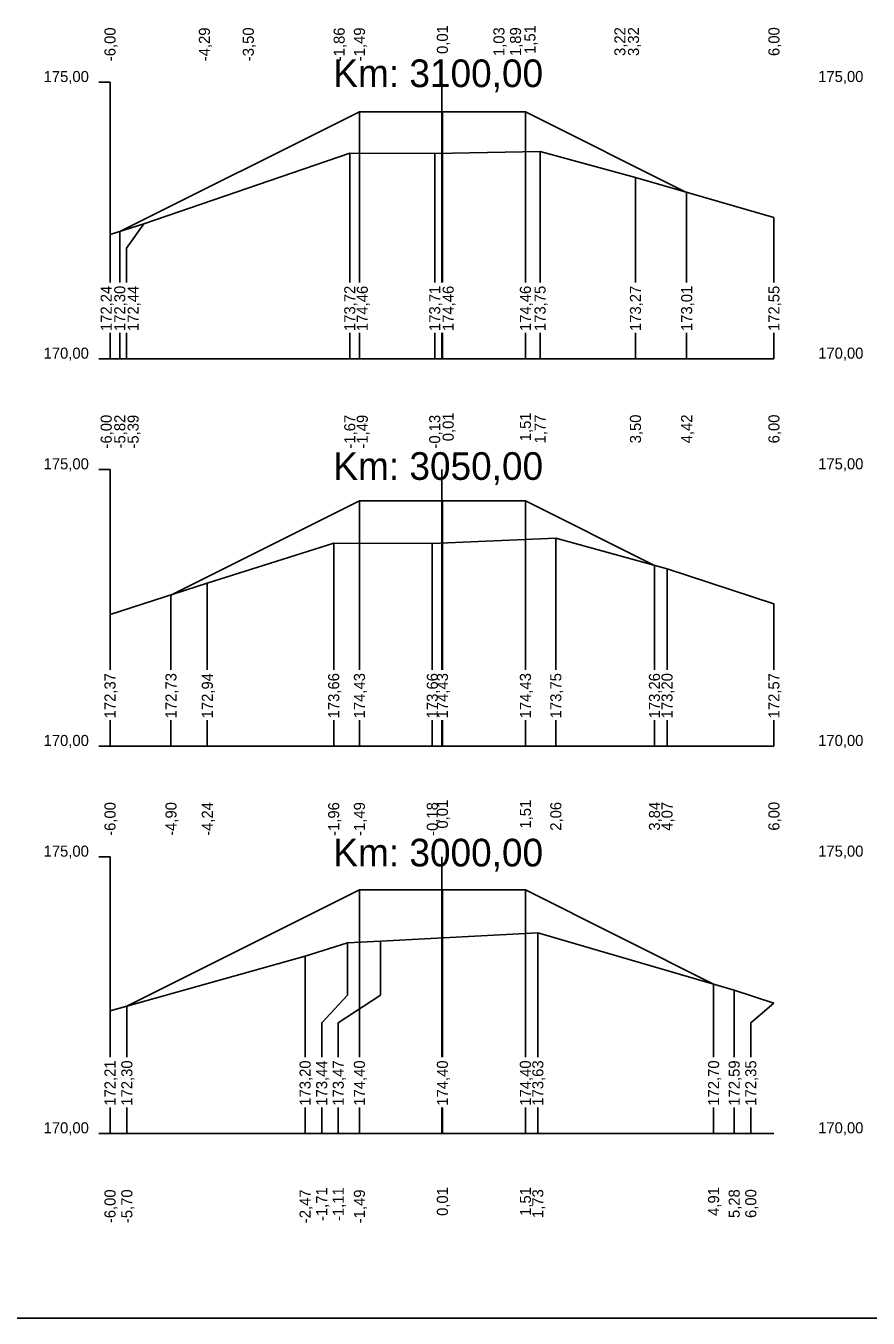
# Model space of a CAD drawing. Extents: x -614174 to -599765, y -1185887 to -1181080.
# Drawn here: x -601047.91 to -601032.69, y -1184533.61 to -1184510.25 of the extents above; entities that cross this region are included whole.
import ezdxf

# ---------------------------------------------------------------- set-up
doc = ezdxf.new("R2010")
doc.units = 0
for name, color, linetype in [('11', 7, 'Continuous'), ('16', 7, 'Continuous'), ('21', 7, 'Continuous'), ('28', 7, 'Continuous'), ('59', 7, 'Continuous'), ('8', 7, 'Continuous'), ('návrh', 7, 'Continuous')]:
    doc.layers.add(name, color=color, linetype=linetype)

msp = doc.modelspace()

# ---------------------------------------------------------------- linework, layer by layer
for points in [[(-601046.212, -1184513.972), (-601041.881, -1184511.806), (-601040.381, -1184511.806), (-601038.881, -1184511.806), (-601035.966, -1184513.264)], [(-601041.881, -1184511.806), (-601041.881, -1184511.806), (-601041.881, -1184511.806)], [(-601040.381, -1184511.806), (-601040.381, -1184511.806), (-601040.381, -1184511.806)], [(-601038.881, -1184511.806), (-601038.881, -1184511.806), (-601038.881, -1184511.806)], [(-601046.389, -1184514.028), (-601045.775, -1184513.834), (-601042.055, -1184512.555), (-601040.52, -1184512.559), (-601038.616, -1184512.523), (-601036.891, -1184512.998), (-601034.389, -1184513.717)], [(-601046.212, -1184513.972), (-601046.212, -1184513.972), (-601046.212, -1184513.972)], [(-601045.287, -1184520.541), (-601041.881, -1184518.838), (-601040.381, -1184518.838), (-601038.881, -1184518.838), (-601036.548, -1184520.005)], [(-601041.881, -1184518.838), (-601041.881, -1184518.838), (-601041.881, -1184518.838)], [(-601040.381, -1184518.838), (-601040.381, -1184518.838), (-601040.381, -1184518.838)], [(-601038.881, -1184518.838), (-601038.881, -1184518.838), (-601038.881, -1184518.838)], [(-601046.389, -1184520.896), (-601044.63, -1184520.329), (-601042.346, -1184519.605), (-601040.564, -1184519.611), (-601038.331, -1184519.515), (-601036.321, -1184520.067), (-601034.389, -1184520.702)], [(-601045.286, -1184520.541), (-601045.287, -1184520.541), (-601045.287, -1184520.541)], [(-601046.085, -1184527.972), (-601041.881, -1184525.87), (-601040.381, -1184525.87), (-601038.881, -1184525.87), (-601035.479, -1184527.571)], [(-601041.881, -1184525.87), (-601041.881, -1184525.87), (-601041.881, -1184525.87)], [(-601040.381, -1184525.87), (-601040.381, -1184525.87), (-601040.381, -1184525.87)], [(-601038.881, -1184525.87), (-601038.881, -1184525.87), (-601038.881, -1184525.87)], [(-601046.389, -1184528.057), (-601042.863, -1184527.069), (-601042.099, -1184526.825), (-601041.501, -1184526.799), (-601038.656, -1184526.644), (-601035.107, -1184527.68), (-601034.389, -1184527.916)], [(-601046.086, -1184527.972), (-601046.085, -1184527.972), (-601046.085, -1184527.972)]]:
    msp.add_lwpolyline(points)
at = {"layer": '11'}
for points in [[(-601041.881, -1184511.806), (-601041.881, -1184513.77), (-601041.881, -1184514.27), (-601041.881, -1184514.892)], [(-601040.381, -1184511.806), (-601040.381, -1184513.77), (-601040.381, -1184514.27), (-601040.381, -1184514.892)], [(-601038.881, -1184511.806), (-601038.881, -1184513.77), (-601038.881, -1184514.27), (-601038.881, -1184514.892)], [(-601038.616, -1184512.523), (-601038.616, -1184513.77), (-601038.616, -1184514.27), (-601038.616, -1184514.892)], [(-601042.055, -1184512.555), (-601042.055, -1184513.77), (-601042.055, -1184514.27), (-601042.055, -1184514.892)], [(-601040.52, -1184512.559), (-601040.52, -1184513.77), (-601040.52, -1184514.27), (-601040.52, -1184514.892)], [(-601036.891, -1184512.998), (-601036.891, -1184513.77), (-601036.891, -1184514.27), (-601036.891, -1184514.892)], [(-601035.966, -1184513.264), (-601035.966, -1184513.77), (-601035.966, -1184514.27), (-601035.966, -1184514.892)], [(-601046.389, -1184514.028), (-601046.389, -1184513.77), (-601046.389, -1184514.27), (-601046.389, -1184514.892)], [(-601045.775, -1184513.834), (-601045.775, -1184513.834), (-601046.089, -1184514.27), (-601046.089, -1184514.892)], [(-601034.389, -1184513.717), (-601034.389, -1184513.77), (-601034.389, -1184514.27), (-601034.389, -1184514.892)], [(-601046.212, -1184513.984), (-601046.212, -1184514.27), (-601046.212, -1184514.892)], [(-601046.389, -1184515.8), (-601046.389, -1184516.27)], [(-601046.212, -1184515.8), (-601046.212, -1184516.27)], [(-601046.089, -1184515.8), (-601046.089, -1184516.27)], [(-601042.055, -1184515.8), (-601042.055, -1184516.27)], [(-601041.881, -1184515.8), (-601041.881, -1184516.27)], [(-601040.52, -1184515.8), (-601040.52, -1184516.27)], [(-601040.381, -1184515.8), (-601040.381, -1184516.27)], [(-601038.881, -1184515.8), (-601038.881, -1184516.27)], [(-601038.616, -1184515.8), (-601038.616, -1184516.27)], [(-601036.891, -1184515.8), (-601036.891, -1184516.27)], [(-601035.966, -1184515.8), (-601035.966, -1184516.27)], [(-601034.389, -1184515.8), (-601034.389, -1184516.27)], [(-601041.881, -1184518.838), (-601041.881, -1184520.77), (-601041.881, -1184521.27), (-601041.881, -1184521.892)], [(-601040.381, -1184518.838), (-601040.381, -1184520.77), (-601040.381, -1184521.27), (-601040.381, -1184521.892)], [(-601038.881, -1184518.838), (-601038.881, -1184520.77), (-601038.881, -1184521.27), (-601038.881, -1184521.892)], [(-601038.331, -1184519.515), (-601038.331, -1184520.77), (-601038.331, -1184521.27), (-601038.331, -1184521.892)], [(-601042.346, -1184519.605), (-601042.346, -1184520.77), (-601042.346, -1184521.27), (-601042.346, -1184521.892)], [(-601040.564, -1184519.611), (-601040.564, -1184520.77), (-601040.564, -1184521.27), (-601040.564, -1184521.892)], [(-601036.548, -1184520.005), (-601036.548, -1184520.77), (-601036.548, -1184521.27), (-601036.548, -1184521.892)], [(-601036.321, -1184520.067), (-601036.321, -1184520.77), (-601036.321, -1184521.27), (-601036.321, -1184521.892)], [(-601044.63, -1184520.329), (-601044.63, -1184520.77), (-601044.63, -1184521.27), (-601044.63, -1184521.892)], [(-601045.287, -1184520.541), (-601045.287, -1184520.77), (-601045.287, -1184521.27), (-601045.287, -1184521.892)], [(-601034.389, -1184520.702), (-601034.389, -1184520.77), (-601034.389, -1184521.27), (-601034.389, -1184521.892)], [(-601046.389, -1184520.896), (-601046.389, -1184520.77), (-601046.389, -1184521.27), (-601046.389, -1184521.892)], [(-601046.389, -1184522.8), (-601046.389, -1184523.27)], [(-601045.287, -1184522.8), (-601045.287, -1184523.27)], [(-601044.63, -1184522.8), (-601044.63, -1184523.27)], [(-601042.346, -1184522.8), (-601042.346, -1184523.27)], [(-601041.881, -1184522.8), (-601041.881, -1184523.27)], [(-601040.564, -1184522.8), (-601040.564, -1184523.27)], [(-601040.381, -1184522.8), (-601040.381, -1184523.27)], [(-601038.881, -1184522.8), (-601038.881, -1184523.27)], [(-601038.331, -1184522.8), (-601038.331, -1184523.27)], [(-601036.548, -1184522.8), (-601036.548, -1184523.27)], [(-601036.321, -1184522.8), (-601036.321, -1184523.27)], [(-601034.389, -1184522.8), (-601034.389, -1184523.27)], [(-601041.881, -1184525.87), (-601041.881, -1184527.77), (-601041.881, -1184528.27), (-601041.881, -1184528.892)], [(-601040.381, -1184525.87), (-601040.381, -1184527.77), (-601040.381, -1184528.27), (-601040.381, -1184528.892)], [(-601038.881, -1184525.87), (-601038.881, -1184527.77), (-601038.881, -1184528.27), (-601038.881, -1184528.892)], [(-601038.656, -1184526.644), (-601038.656, -1184527.77), (-601038.656, -1184528.27), (-601038.656, -1184528.892)], [(-601042.099, -1184526.825), (-601042.099, -1184527.77), (-601042.563, -1184528.27), (-601042.563, -1184528.892)], [(-601041.501, -1184526.799), (-601041.501, -1184527.77), (-601042.263, -1184528.27), (-601042.263, -1184528.892)], [(-601042.863, -1184527.069), (-601042.863, -1184527.77), (-601042.863, -1184528.27), (-601042.863, -1184528.892)], [(-601035.479, -1184527.571), (-601035.479, -1184527.77), (-601035.479, -1184528.27), (-601035.479, -1184528.892)], [(-601035.107, -1184527.68), (-601035.107, -1184527.77), (-601035.107, -1184528.27), (-601035.107, -1184528.892)], [(-601046.389, -1184528.057), (-601046.389, -1184527.77), (-601046.389, -1184528.27), (-601046.389, -1184528.892)], [(-601034.389, -1184527.916), (-601034.807, -1184528.27), (-601034.807, -1184528.892)], [(-601046.085, -1184527.972), (-601046.085, -1184528.892)], [(-601046.389, -1184529.8), (-601046.389, -1184530.27)], [(-601046.085, -1184529.8), (-601046.085, -1184530.27)], [(-601042.863, -1184529.8), (-601042.863, -1184530.27)], [(-601042.563, -1184529.8), (-601042.563, -1184530.27)], [(-601042.263, -1184529.8), (-601042.263, -1184530.27)], [(-601041.881, -1184529.8), (-601041.881, -1184530.27)], [(-601040.381, -1184529.8), (-601040.381, -1184530.27)], [(-601038.881, -1184529.8), (-601038.881, -1184530.27)], [(-601038.656, -1184529.8), (-601038.656, -1184530.27)], [(-601035.479, -1184529.8), (-601035.479, -1184530.27)], [(-601035.107, -1184529.8), (-601035.107, -1184530.27)], [(-601034.807, -1184529.8), (-601034.807, -1184530.27)]]:
    msp.add_lwpolyline(points, dxfattribs=at)
at = {"layer": '16'}
for p, q in [((-601046.389, -1184516.27), (-601034.389, -1184516.27)), ((-601046.389, -1184523.27), (-601034.389, -1184523.27)), ((-601046.389, -1184530.27), (-601034.389, -1184530.27))]:
    msp.add_line(p, q, dxfattribs=at)
for points in [[(-601035.966, -1184513.264), (-601035.966, -1184513.264), (-601035.967, -1184513.264)], [(-601036.549, -1184520.005), (-601036.548, -1184520.005), (-601036.548, -1184520.005)], [(-601035.478, -1184527.572), (-601035.479, -1184527.571), (-601035.479, -1184527.571)]]:
    msp.add_lwpolyline(points, dxfattribs=at)
at = {"layer": '21'}
for p, q in [((-601046.589, -1184511.27), (-601046.389, -1184511.27)), ((-601046.589, -1184516.27), (-601046.389, -1184516.27)), ((-601046.589, -1184518.27), (-601046.389, -1184518.27)), ((-601046.589, -1184523.27), (-601046.389, -1184523.27)), ((-601046.589, -1184525.27), (-601046.389, -1184525.27)), ((-601046.589, -1184530.27), (-601046.389, -1184530.27))]:
    msp.add_line(p, q, dxfattribs=at)
at = {"layer": '28'}
for p, q in [((-601040.389, -1184514.892), (-601040.389, -1184511.27)), ((-601040.389, -1184516.27), (-601040.389, -1184515.8)), ((-601040.389, -1184521.892), (-601040.389, -1184518.27)), ((-601040.389, -1184523.27), (-601040.389, -1184522.8)), ((-601040.389, -1184528.892), (-601040.389, -1184525.27)), ((-601040.389, -1184530.27), (-601040.389, -1184529.8))]:
    msp.add_line(p, q, dxfattribs=at)
at = {"layer": '8'}
for p, q in [((-601046.389, -1184514.892), (-601046.389, -1184511.27)), ((-601046.389, -1184516.27), (-601046.389, -1184515.8)), ((-601046.389, -1184521.892), (-601046.389, -1184518.27)), ((-601046.389, -1184523.27), (-601046.389, -1184522.8)), ((-601046.389, -1184528.892), (-601046.389, -1184525.27)), ((-601046.389, -1184530.27), (-601046.389, -1184529.8))]:
    msp.add_line(p, q, dxfattribs=at)
at = {"layer": 'návrh'}
msp.add_line((-601048.944, -1184533.61), (-601027.944, -1184533.61), dxfattribs=at)

# ---------------------------------------------------------------- texts
at = {"layer": '16'}
for s, p in [('172,24', (-601046.358, -1184515.77)), ('172,30', (-601046.112, -1184515.77)), ('172,44', (-601045.871, -1184515.77)), ('173,72', (-601041.955, -1184515.77)), ('174,46', (-601041.729, -1184515.77)), ('173,71', (-601040.42, -1184515.77)), ('174,46', (-601040.177, -1184515.77)), ('174,46', (-601038.781, -1184515.77)), ('173,75', (-601038.516, -1184515.77)), ('173,27', (-601036.791, -1184515.77)), ('173,01', (-601035.866, -1184515.77)), ('172,55', (-601034.289, -1184515.77)), ('172,37', (-601046.289, -1184522.77)), ('172,73', (-601045.187, -1184522.77)), ('172,94', (-601044.53, -1184522.77)), ('173,66', (-601042.246, -1184522.77)), ('174,43', (-601041.781, -1184522.77)), ('173,66', (-601040.464, -1184522.77)), ('174,43', (-601040.281, -1184522.77)), ('174,43', (-601038.781, -1184522.77)), ('173,75', (-601038.231, -1184522.77)), ('173,26', (-601036.448, -1184522.77)), ('173,20', (-601036.221, -1184522.77)), ('172,57', (-601034.289, -1184522.77)), ('172,21', (-601046.289, -1184529.77)), ('172,30', (-601045.985, -1184529.77)), ('173,20', (-601042.763, -1184529.77)), ('173,44', (-601042.463, -1184529.77)), ('173,47', (-601042.163, -1184529.77)), ('174,40', (-601041.781, -1184529.77)), ('174,40', (-601040.281, -1184529.77)), ('174,40', (-601038.781, -1184529.77)), ('173,63', (-601038.556, -1184529.77)), ('172,70', (-601035.379, -1184529.77)), ('172,59', (-601035.007, -1184529.77)), ('172,35', (-601034.707, -1184529.77))]:
    msp.add_text(s, height=0.2, rotation=90, dxfattribs=at).set_placement(p)
at = {"layer": '21'}
for s, p in [('175,00', (-601047.589, -1184511.27)), ('175,00', (-601033.589, -1184511.27)), ('170,00', (-601047.589, -1184516.27)), ('170,00', (-601033.589, -1184516.27)), ('175,00', (-601047.589, -1184518.27)), ('175,00', (-601033.589, -1184518.27)), ('170,00', (-601047.589, -1184523.27)), ('170,00', (-601033.589, -1184523.27)), ('175,00', (-601047.589, -1184525.27)), ('175,00', (-601033.589, -1184525.27)), ('170,00', (-601047.589, -1184530.27)), ('170,00', (-601033.589, -1184530.27))]:
    msp.add_text(s, height=0.2, dxfattribs=at).set_placement(p)
at = {"layer": '28'}
for s, p in [('Km: 3100,00', (-601042.352, -1184511.362)), ('Km: 3050,00', (-601042.352, -1184518.46)), ('Km: 3000,00', (-601042.352, -1184525.446))]:
    msp.add_text(s, height=0.5, dxfattribs=at).set_placement(p)
at = {"layer": '59'}
for s, p in [('-6,00', (-601046.289, -1184510.893)), ('-4,29', (-601044.583, -1184510.894)), ('-3,50', (-601043.789, -1184510.893)), ('-1,86', (-601042.147, -1184510.894)), ('-1,49', (-601041.781, -1184510.894)), ('0,01', (-601040.281, -1184510.762)), ('1,03', (-601039.259, -1184510.801)), ('1,89', (-601038.959, -1184510.801)), ('1,51', (-601038.698, -1184510.762)), ('3,22', (-601037.072, -1184510.799)), ('3,32', (-601036.827, -1184510.799)), ('6,00', (-601034.289, -1184510.8)), ('-6,00', (-601046.358, -1184517.893)), ('-5,82', (-601046.112, -1184517.892)), ('-5,39', (-601045.871, -1184517.894)), ('-1,67', (-601041.955, -1184517.894)), ('-1,49', (-601041.729, -1184517.894)), ('-0,13', (-601040.42, -1184517.894)), ('0,01', (-601040.177, -1184517.762)), ('1,51', (-601038.781, -1184517.762)), ('1,77', (-601038.516, -1184517.801)), ('3,50', (-601036.791, -1184517.8)), ('4,42', (-601035.866, -1184517.799)), ('6,00', (-601034.289, -1184517.8)), ('-6,00', (-601046.289, -1184524.893)), ('-4,90', (-601045.187, -1184524.893)), ('-4,24', (-601044.53, -1184524.893)), ('-1,96', (-601042.246, -1184524.894)), ('-1,49', (-601041.781, -1184524.894)), ('-0,18', (-601040.464, -1184524.894)), ('0,01', (-601040.281, -1184524.762)), ('1,51', (-601038.781, -1184524.762)), ('2,06', (-601038.231, -1184524.801)), ('3,84', (-601036.448, -1184524.8)), ('4,07', (-601036.221, -1184524.801)), ('6,00', (-601034.289, -1184524.8)), ('-6,00', (-601046.289, -1184531.893)), ('-5,70', (-601045.985, -1184531.893)), ('-2,47', (-601042.763, -1184531.894)), ('-1,71', (-601042.463, -1184531.855)), ('-1,11', (-601042.163, -1184531.855)), ('-1,49', (-601041.781, -1184531.894)), ('0,01', (-601040.281, -1184531.762)), ('1,51', (-601038.781, -1184531.762)), ('1,73', (-601038.556, -1184531.801)), ('4,91', (-601035.379, -1184531.762)), ('5,28', (-601035.007, -1184531.801)), ('6,00', (-601034.707, -1184531.8))]:
    msp.add_text(s, height=0.2, rotation=90, dxfattribs=at).set_placement(p)

doc.saveas('drawing.dxf')
